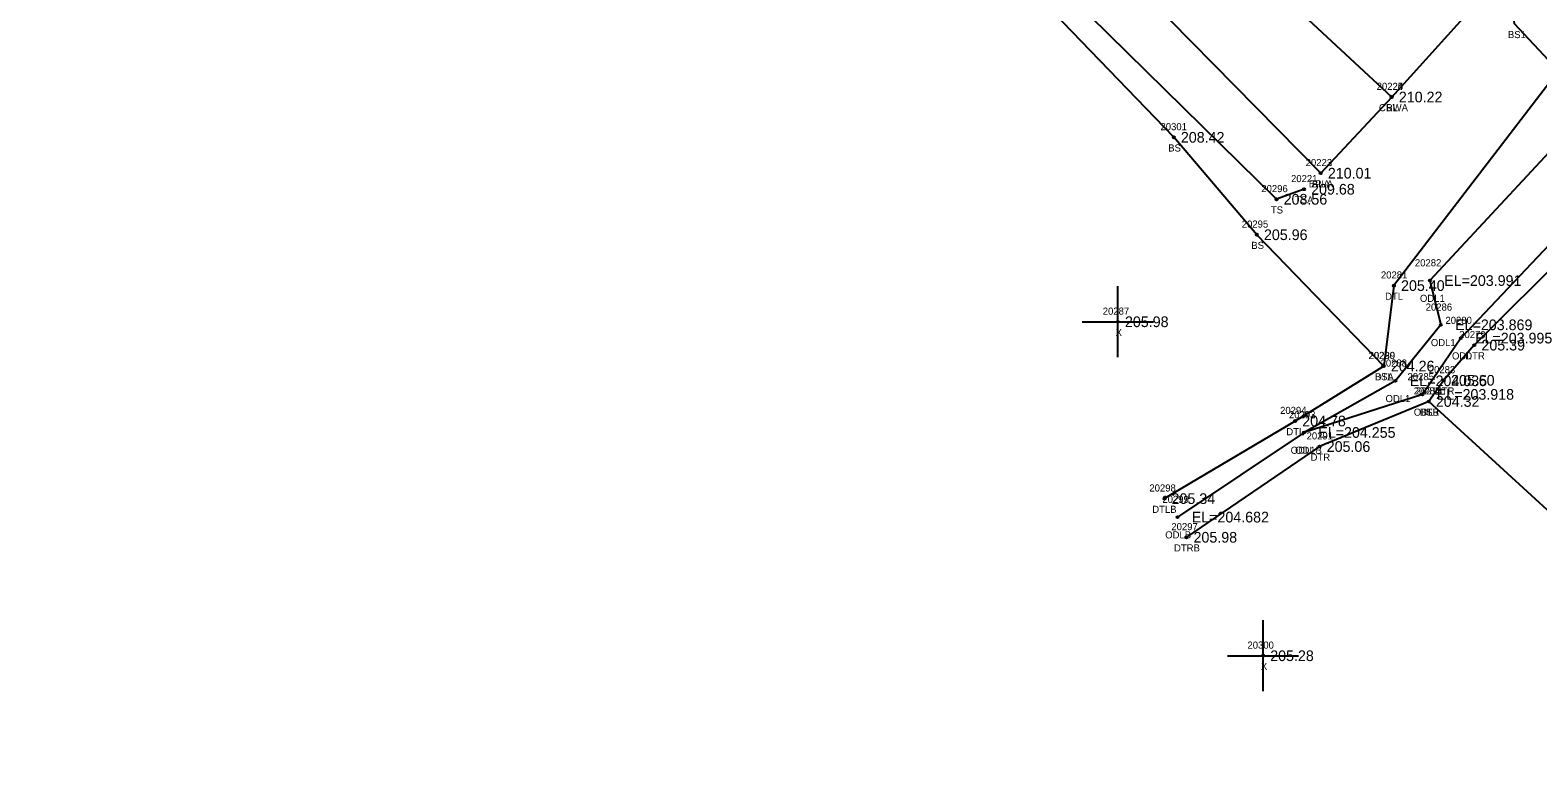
# Model space of a CAD drawing. Extents: x 2260230 to 2261304, y 1064626 to 1065587.
# Drawn here: x 2260269.2 to 2260481.3, y 1065284.3 to 1065386.5 of the extents above; entities that cross this region are included whole.
import ezdxf

# ---------------------------------------------------------------- set-up
doc = ezdxf.new("R2010")
doc.units = 0
for name, color, linetype in [('RD_DTM_BkLn1', 7, 'Continuous'), ('RD_DTM_BkLn2', 7, 'Continuous'), ('RD_DTM_BkLn_txCode', 7, 'Continuous'), ('RD_EX_H2O', 7, 'Continuous'), ('RD_EX_H2O_txCode', 7, 'Continuous'), ('RD_EX_Misc', 7, 'Continuous'), ('RD_EX_Misc_txCode', 7, 'Continuous'), ('RD_EX_Road', 7, 'Continuous'), ('RD_EX_Road_txCode', 7, 'Continuous'), ('RD_EX_TX_H2O_ELEV', 7, 'Continuous'), ('RD_EX_TX_Misc_ELEV', 7, 'Continuous'), ('RD_EX_TX_Road_ELEV', 7, 'Continuous'), ('RD_HC_Survey_ELEV', 7, 'Continuous'), ('RD_HC_Survey_txCode', 7, 'Continuous'), ('RD_SMD_Locator', 7, 'Continuous')]:
    doc.layers.add(name, color=color, linetype=linetype)

msp = doc.modelspace()

# ---------------------------------------------------------------- linework, layer by layer
at = {"layer": 'RD_DTM_BkLn1'}
for points in [[(2260460.75, 1065377.06), (2260391.17, 1065441.67), (2260322.55, 1065505.55), (2260275.44, 1065548.93)], [(2260450.76, 1065366.34), (2260460.75, 1065377.06), (2260471.29, 1065388.66)]]:
    msp.add_lwpolyline(points, dxfattribs=at)
at = {"layer": 'RD_DTM_BkLn2'}
for points in [[(2260484.22, 1065380.75), (2260478.04, 1065387.35), (2260476.93, 1065397.87), (2260411.32, 1065463.45), (2260400.24, 1065480.84)], [(2260448.41, 1065364.08), (2260444.54, 1065362.67), (2260384.24, 1065421.93)], [(2260459.63, 1065339.19), (2260441.77, 1065357.68), (2260430.08, 1065371.39), (2260383.23, 1065420.03)], [(2260769.94, 1065084.22), (2260759.25, 1065090.93), (2260723.51, 1065114.68), (2260656.37, 1065173.06), (2260640.88, 1065186.75), (2260590.19, 1065225.63), (2260553.18, 1065256.82), (2260516.06, 1065288.21), (2260487.07, 1065314.86), (2260465.96, 1065334.21)]]:
    msp.add_lwpolyline(points, dxfattribs=at)
at = {"layer": 'RD_EX_H2O'}
for points in [[(2260512.07, 1065385.67), (2260499.61, 1065384.39), (2260490.39, 1065378.06), (2260484.22, 1065380.75), (2260461.06, 1065350.52), (2260459.63, 1065339.19), (2260447.16, 1065331.46), (2260428.77, 1065320.54)], [(2260512.19, 1065383.47), (2260503.16, 1065382.63), (2260491.6, 1065374.02), (2260496.18, 1065370.27), (2260470.47, 1065343.13), (2260465.09, 1065335.21), (2260448.41, 1065329.85), (2260430.6, 1065317.94)], [(2260646.56, 1065296.38), (2260610.59, 1065289.37), (2260597.58, 1065295.34), (2260590.32, 1065312.1), (2260558.95, 1065340.75), (2260514.3, 1065379.95), (2260504.3, 1065379.76), (2260497.13, 1065374.25), (2260499.47, 1065369.14), (2260472.37, 1065342.14), (2260468.09, 1065337.19), (2260465.96, 1065334.21), (2260450.6, 1065327.87), (2260431.86, 1065315.1)], [(2260491.6, 1065374.02), (2260489.1, 1065375.96), (2260466.13, 1065351.23), (2260467.67, 1065345), (2260461.29, 1065337.12), (2260448.41, 1065329.85)]]:
    msp.add_lwpolyline(points, dxfattribs=at)
at = {"layer": 'RD_EX_Misc'}
for p, q in [((2260422.21, 1065340.43), (2260422.21, 1065350.43)), ((2260417.21, 1065345.43), (2260427.21, 1065345.43)), ((2260442.65, 1065293.43), (2260442.65, 1065303.43)), ((2260437.65, 1065298.43), (2260447.65, 1065298.43))]:
    msp.add_line(p, q, dxfattribs=at)
at = {"layer": 'RD_EX_Road'}
msp.add_lwpolyline([(2260450.76, 1065366.34), (2260384.25, 1065433.92), (2260316.12, 1065498), (2260269.16, 1065540.98)], dxfattribs=at)
at = {"layer": 'RD_SMD_Locator'}
for centre in [(2260460.75, 1065377.06), (2260460.75, 1065377.06), (2260430.08, 1065371.39), (2260450.76, 1065366.34), (2260450.76, 1065366.34), (2260448.41, 1065364.08), (2260444.54, 1065362.67), (2260441.77, 1065357.68), (2260461.06, 1065350.52), (2260466.13, 1065351.23), (2260422.21, 1065345.43), (2260467.67, 1065345), (2260470.47, 1065343.13), (2260472.37, 1065342.14), (2260459.63, 1065339.19), (2260459.63, 1065339.19), (2260461.29, 1065337.12), (2260468.09, 1065337.19), (2260465.09, 1065335.21), (2260465.96, 1065334.21), (2260465.96, 1065334.21), (2260447.16, 1065331.46), (2260448.41, 1065329.85), (2260448.41, 1065329.85), (2260450.6, 1065327.87), (2260428.77, 1065320.54), (2260430.6, 1065317.94), (2260431.86, 1065315.1), (2260442.65, 1065298.43)]:
    msp.add_circle(centre, 0.15, dxfattribs=at)

# ---------------------------------------------------------------- texts
at = {"layer": 'RD_DTM_BkLn_txCode'}
for s, p in [('BS1', (2260477.1, 1065385.35)), ('20225', (2260458.63, 1065378.06)), ('BL', (2260459.99, 1065375.06)), ('20301', (2260428.21, 1065372.39)), ('BS', (2260429.3, 1065369.39)), ('20223', (2260448.64, 1065367.34)), ('20296', (2260442.4, 1065363.67)), ('20221', (2260446.58, 1065365.08)), ('BLA', (2260449.52, 1065364.34)), ('TSA', (2260447.13, 1065362.08)), ('TS', (2260443.75, 1065360.67)), ('20295', (2260439.65, 1065358.68)), ('BS', (2260440.99, 1065355.68)), ('20290', (2260457.47, 1065340.19)), ('BSA', (2260458.36, 1065337.19)), ('20213', (2260464.13, 1065335.21)), ('BSB', (2260464.71, 1065332.21))]:
    msp.add_text(s, height=1, dxfattribs=at).set_placement(p)
at = {"layer": 'RD_EX_H2O_txCode'}
for s, p in [('20282', (2260464.01, 1065353.23)), ('20281', (2260459.23, 1065351.52)), ('DTL', (2260459.82, 1065348.52)), ('ODL1', (2260464.72, 1065348.23)), ('20286', (2260465.53, 1065347)), ('20280', (2260468.31, 1065345.13)), ('ODL1', (2260466.26, 1065342)), ('20279', (2260470.25, 1065343.14)), ('20289', (2260457.51, 1065340.19)), ('ODL', (2260469.23, 1065340.13)), ('DTR', (2260471.1, 1065340.14)), ('20288', (2260459.18, 1065339.12)), ('20283', (2260465.97, 1065338.19)), ('DTL', (2260458.38, 1065337.19)), ('20285', (2260462.97, 1065337.21)), ('ODL1', (2260459.88, 1065334.12)), ('20284', (2260463.85, 1065335.21)), ('DTR', (2260466.82, 1065335.19)), ('20294', (2260445.04, 1065332.46)), ('20292', (2260446.29, 1065331.85)), ('20293', (2260446.29, 1065331.85)), ('ODL', (2260463.85, 1065332.21)), ('DTR', (2260464.7, 1065332.21)), ('DTL', (2260445.92, 1065329.46)), ('20291', (2260448.77, 1065328.87)), ('ODL1B', (2260446.53, 1065326.85)), ('ODL', (2260447.16, 1065326.85)), ('DTR', (2260449.33, 1065325.87)), ('20298', (2260426.65, 1065321.54)), ('20299', (2260428.48, 1065319.94)), ('DTLB', (2260427.05, 1065318.54)), ('ODLB', (2260428.88, 1065314.94)), ('20297', (2260429.74, 1065316.1)), ('DTRB', (2260430.12, 1065313.1))]:
    msp.add_text(s, height=1, dxfattribs=at).set_placement(p)
at = {"layer": 'RD_EX_Misc_txCode'}
for s, p in [('20287', (2260420.09, 1065346.43)), ('X', (2260421.9, 1065343.43)), ('20300', (2260440.45, 1065299.43)), ('X', (2260442.34, 1065296.43))]:
    msp.add_text(s, height=1, dxfattribs=at).set_placement(p)
at = {"layer": 'RD_EX_Road_txCode'}
for s, p in [('20222', (2260448.64, 1065367.34)), ('EPLA', (2260449.07, 1065364.34))]:
    msp.add_text(s, height=1, dxfattribs=at).set_placement(p)
at = {"layer": 'RD_EX_TX_H2O_ELEV'}
for s, p in [('EL=203.991', (2260468.13, 1065350.48)), ('205.40', (2260462.06, 1065349.77)), ('EL=203.869', (2260469.67, 1065344.25)), ('EL=203.995', (2260472.47, 1065342.38)), ('205.39', (2260473.37, 1065341.39)), ('204.26', (2260460.63, 1065338.44)), ('EL=204.035', (2260463.29, 1065336.37)), ('205.60', (2260469.09, 1065336.44)), ('204.32', (2260466.96, 1065333.46)), ('EL=203.918', (2260467.09, 1065334.46)), ('204.78', (2260448.16, 1065330.71)), ('EL=204.255', (2260450.41, 1065329.1)), ('EL=204.255', (2260450.41, 1065329.1)), ('205.06', (2260451.6, 1065327.12)), ('205.34', (2260429.77, 1065319.79)), ('EL=204.682', (2260432.6, 1065317.19)), ('205.98', (2260432.86, 1065314.35))]:
    msp.add_text(s, height=1.5, dxfattribs=at).set_placement(p)
at = {"layer": 'RD_EX_TX_Misc_ELEV'}
for s, p in [('210.22', (2260461.75, 1065376.31)), ('208.42', (2260431.08, 1065370.64)), ('210.01', (2260451.76, 1065365.59)), ('209.68', (2260449.41, 1065363.33)), ('208.56', (2260445.54, 1065361.92)), ('205.96', (2260442.77, 1065356.93)), ('205.98', (2260423.21, 1065344.68)), ('204.26', (2260460.63, 1065338.44)), ('204.32', (2260466.96, 1065333.46)), ('205.28', (2260443.65, 1065297.68))]:
    msp.add_text(s, height=1.5, dxfattribs=at).set_placement(p)
at = {"layer": 'RD_EX_TX_Road_ELEV'}
msp.add_text('210.01', height=1.5, dxfattribs=at).set_placement((2260451.76, 1065365.59))
at = {"layer": 'RD_HC_Survey_ELEV'}
msp.add_text('210.22', height=1.5, dxfattribs=at).set_placement((2260461.75, 1065376.31))
at = {"layer": 'RD_HC_Survey_txCode'}
for s, p in [('20224', (2260458.63, 1065378.06)), ('CRWA', (2260458.95, 1065375.06))]:
    msp.add_text(s, height=1, dxfattribs=at).set_placement(p)

doc.saveas('drawing.dxf')
